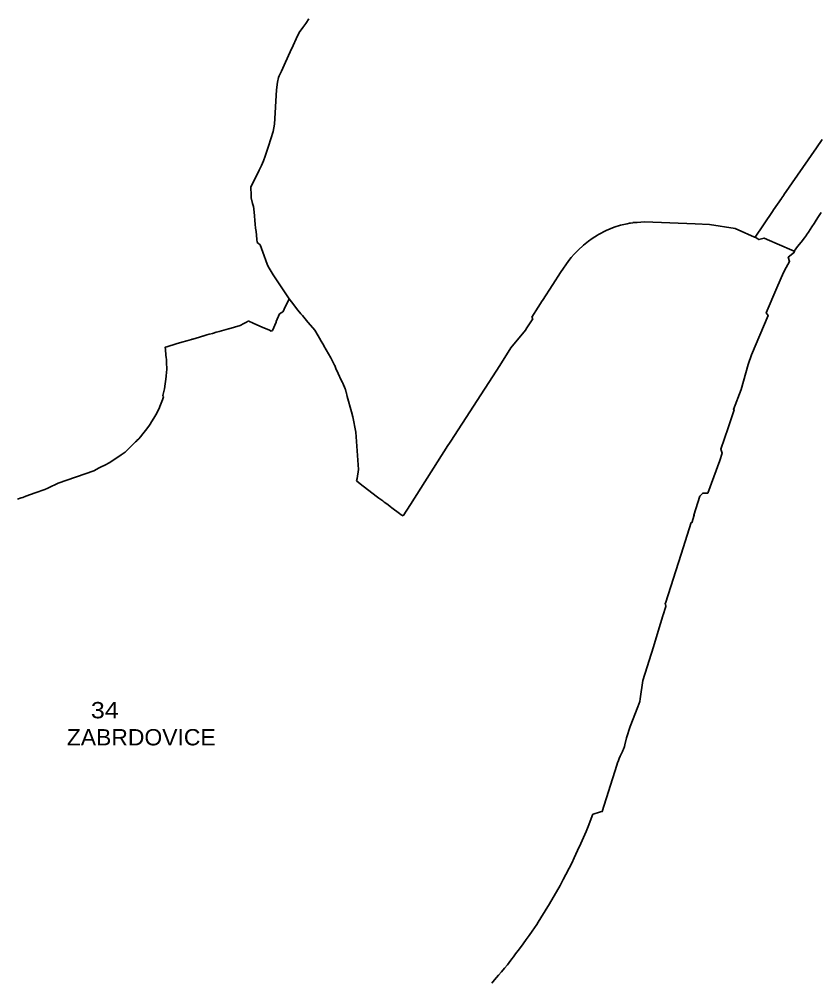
# Model space of a CAD drawing. Extents: x -610940 to -588976, y -1170376 to -1149800.
# Drawn here: x -597067 to -595838, y -1160628 to -1159152 of the extents above; entities that cross this region are included whole.
import ezdxf

# ---------------------------------------------------------------- set-up
doc = ezdxf.new("R2010")
doc.units = 0
doc.header["$LTSCALE"] = 10
doc.layers.add('54', color=7, linetype='Continuous', lineweight=35)
doc.layers.add('55', color=7, linetype='Continuous')
doc.layers.add('56', color=7, linetype='Continuous')

msp = doc.modelspace()

# ---------------------------------------------------------------- linework, layer by layer
at = {"layer": '54'}
for p, q in [((-596622.61, -1159151.93), (-596627.61, -1159158.97)), ((-596670.78, -1159248.89), (-596672.14, -1159260.81)), ((-596669.26, -1159241.48), (-596670.78, -1159248.89)), ((-596668.25, -1159239.42), (-596669.26, -1159241.48)), ((-596672.14, -1159260.81), (-596675.34, -1159313.09)), ((-596677.3, -1159324.73), (-596684.58, -1159347.14)), ((-596675.34, -1159313.09), (-596677.3, -1159324.73)), ((-596702.54, -1159391.38), (-596707.39, -1159401.38)), ((-596711.3, -1159425.25), (-596711.3, -1159426.31)), ((-596707.71, -1159439.7), (-596706.94, -1159443.07)), ((-596706.94, -1159443.07), (-596706.02, -1159454.02)), ((-596706.02, -1159454.02), (-596705.4, -1159460.88)), ((-595912.08, -1159446.96), (-595938.72, -1159486.54)), ((-596705.4, -1159460.88), (-596704.9, -1159466.39)), ((-596704.9, -1159466.39), (-596704.33, -1159472.84)), ((-596166.92, -1159476.5), (-596154.58, -1159471.12)), ((-596154.58, -1159471.12), (-596144.82, -1159468.1)), ((-596144.82, -1159468.1), (-596142.36, -1159467.57)), ((-596142.36, -1159467.57), (-596134.73, -1159465.92)), ((-596134.73, -1159465.92), (-596131.25, -1159465.27)), ((-596131.25, -1159465.27), (-596129.76, -1159465.08)), ((-596129.76, -1159465.08), (-596126.25, -1159464.55)), ((-596126.26, -1159464.26), (-596124.27, -1159464.11)), ((-596126.25, -1159464.55), (-596126.26, -1159464.26)), ((-596124.27, -1159464.11), (-596119.41, -1159463.76)), ((-596119.41, -1159463.76), (-596108.28, -1159462.97)), ((-596108.28, -1159462.97), (-596030.58, -1159465.89)), ((-596030.58, -1159465.89), (-596008.65, -1159467.16)), ((-596008.65, -1159467.16), (-595969.3, -1159473.46)), ((-596704.33, -1159472.84), (-596703.73, -1159477.96)), ((-596703.73, -1159477.96), (-596702.45, -1159489.51)), ((-596188.33, -1159488.39), (-596180.47, -1159483.27)), ((-596180.47, -1159483.27), (-596178.71, -1159482.17)), ((-596178.71, -1159482.17), (-596166.92, -1159476.5)), ((-595969.3, -1159473.46), (-595954.52, -1159479.77)), ((-595954.52, -1159479.77), (-595949.96, -1159481.7)), ((-595949.96, -1159481.7), (-595939.43, -1159486.25)), ((-595939.43, -1159486.25), (-595938.72, -1159486.54)), ((-596702.45, -1159489.51), (-596701.93, -1159494.64)), ((-596701.93, -1159494.64), (-596699.96, -1159496.12)), ((-596699.96, -1159496.12), (-596697.5, -1159498.07)), ((-596697.5, -1159498.07), (-596693.51, -1159509.34)), ((-596209.99, -1159506.34), (-596201.89, -1159498.65)), ((-596201.89, -1159498.65), (-596194.21, -1159492.58)), ((-596194.21, -1159492.58), (-596188.33, -1159488.39)), ((-596693.51, -1159509.34), (-596686.54, -1159527.7)), ((-596220.75, -1159517.91), (-596215.92, -1159512.56)), ((-596215.92, -1159512.56), (-596209.99, -1159506.34)), ((-596686.54, -1159527.7), (-596685.11, -1159531.64)), ((-596237.22, -1159540.52), (-596224.02, -1159522.07)), ((-596224.02, -1159522.07), (-596220.75, -1159517.91)), ((-596685.11, -1159531.64), (-596677.48, -1159544.34)), ((-596677.48, -1159544.34), (-596673.59, -1159550.23)), ((-596248.81, -1159558.89), (-596237.22, -1159540.52)), ((-596673.59, -1159550.23), (-596668.13, -1159558.24)), ((-596668.13, -1159558.24), (-596662.13, -1159567.47)), ((-596264.67, -1159583.62), (-596248.81, -1159558.89)), ((-596662.13, -1159567.47), (-596652.83, -1159581.27)), ((-596660.47, -1159596.66), (-596652.83, -1159581.27)), ((-596652.83, -1159581.27), (-596649.56, -1159585.55)), ((-596649.56, -1159585.55), (-596642.59, -1159594.4)), ((-596271.22, -1159593.87), (-596264.91, -1159584)), ((-596264.91, -1159584), (-596264.67, -1159583.62)), ((-596662.36, -1159600.53), (-596660.47, -1159596.66)), ((-596642.59, -1159594.4), (-596639.92, -1159597.88)), ((-596639.92, -1159597.88), (-596637.13, -1159601.32)), ((-596637.13, -1159601.32), (-596635.14, -1159603.85)), ((-596635.14, -1159603.85), (-596632.74, -1159606.71)), ((-596281.08, -1159609.18), (-596271.22, -1159593.87)), ((-596728.18, -1159621.84), (-596722.26, -1159618.73)), ((-596722.26, -1159618.73), (-596717.36, -1159616.16)), ((-596717.36, -1159616.16), (-596715.74, -1159615.01)), ((-596707.18, -1159618.81), (-596715.74, -1159615.01)), ((-596706.85, -1159618.86), (-596707.18, -1159618.81)), ((-596694.41, -1159624.25), (-596706.85, -1159618.86)), ((-596673.12, -1159616.89), (-596678.57, -1159629.55)), ((-596672.78, -1159616.01), (-596673.12, -1159616.89)), ((-596632.74, -1159606.71), (-596624.17, -1159616.99)), ((-596624.17, -1159616.99), (-596623.82, -1159617.41)), ((-596623.82, -1159617.41), (-596613.43, -1159629.07)), ((-596288.61, -1159625.51), (-596279.48, -1159611.76)), ((-596279.48, -1159611.76), (-596281.08, -1159609.18)), ((-596745.67, -1159626.79), (-596728.18, -1159621.84)), ((-596682.98, -1159629.17), (-596694.41, -1159624.25)), ((-596680.33, -1159630.35), (-596682.98, -1159629.17)), ((-596678.57, -1159629.55), (-596680.33, -1159630.35)), ((-596613.43, -1159629.07), (-596604.99, -1159643.93)), ((-596312.97, -1159656.35), (-596290.81, -1159628.86)), ((-596290.81, -1159628.86), (-596288.61, -1159625.51)), ((-596826.25, -1159649.89), (-596824.65, -1159649.38)), ((-596824.65, -1159649.38), (-596822.46, -1159648.83)), ((-596604.99, -1159643.93), (-596604.21, -1159645.29)), ((-596604.21, -1159645.29), (-596603.95, -1159645.7)), ((-596603.95, -1159645.7), (-596601.51, -1159649.96)), ((-596601.51, -1159649.96), (-596600, -1159652.51)), ((-596600, -1159652.51), (-596599.6, -1159653.28)), ((-596599.6, -1159653.28), (-596596.29, -1159659.04)), ((-596596.29, -1159659.04), (-596596.13, -1159659.35)), ((-596596.13, -1159659.35), (-596589.1, -1159671.61)), ((-596330.09, -1159683.16), (-596312.97, -1159656.35)), ((-596589.1, -1159671.61), (-596583.4, -1159682.61)), ((-596583.4, -1159682.61), (-596583.14, -1159683.31)), ((-596583.14, -1159683.31), (-596581.16, -1159687.69)), ((-596581.16, -1159687.69), (-596577.74, -1159695.26)), ((-596405.27, -1159799.23), (-596335.79, -1159691.87)), ((-596335.79, -1159691.87), (-596330.09, -1159683.16)), ((-596577.74, -1159695.26), (-596573.02, -1159705.51)), ((-596573.02, -1159705.51), (-596571.21, -1159709.48)), ((-596571.21, -1159709.48), (-596570.77, -1159710.41)), ((-596570.77, -1159710.41), (-596566.86, -1159719.06)), ((-596566.86, -1159719.06), (-596566.69, -1159719.63)), ((-596566.69, -1159719.63), (-596565.81, -1159723.06)), ((-596565.81, -1159723.06), (-596565.61, -1159723.77)), ((-596565.61, -1159723.77), (-596563.78, -1159730.55)), ((-596563.78, -1159730.55), (-596557.36, -1159754.38)), ((-596557.36, -1159754.38), (-596555.34, -1159761.89)), ((-596555.34, -1159761.89), (-596550.6, -1159785.52)), ((-596550.6, -1159785.52), (-596546.63, -1159842.66)), ((-596888.42, -1159800.26), (-596902.81, -1159814.44)), ((-596467, -1159896.14), (-596409.48, -1159805.72)), ((-596409.48, -1159805.72), (-596407.06, -1159802.05)), ((-596407.06, -1159802.05), (-596405.27, -1159799.23)), ((-596927.87, -1159831.93), (-596910.5, -1159820.04)), ((-596910.5, -1159820.04), (-596904.56, -1159816.06)), ((-596902.81, -1159814.44), (-596904.56, -1159816.06)), ((-596935.5, -1159835.97), (-596927.87, -1159831.93)), ((-596546.63, -1159842.66), (-596548.93, -1159856.35)), ((-597013.14, -1159866.5), (-597007.32, -1159863.75)), ((-596548.93, -1159856.35), (-596549.59, -1159860.26)), ((-596549.59, -1159860.26), (-596549.23, -1159860.52)), ((-596549.23, -1159860.52), (-596546.98, -1159862.16)), ((-596546.98, -1159862.16), (-596541.49, -1159866.75)), ((-596541.49, -1159866.75), (-596539.64, -1159868.29)), ((-596539.64, -1159868.29), (-596517.64, -1159884.9)), ((-597064, -1159886.29), (-597061.28, -1159885.34)), ((-597056.62, -1159883.72), (-597061.28, -1159885.34)), ((-597027.46, -1159873.28), (-597023.16, -1159871.2)), ((-596517.64, -1159884.9), (-596515.55, -1159886.45)), ((-597069.46, -1159888.21), (-597064, -1159886.29)), ((-596515.55, -1159886.45), (-596509.51, -1159890.91)), ((-596501.2, -1159897.05), (-596506.22, -1159893.22)), ((-596501.2, -1159897.05), (-596498.31, -1159899.21)), ((-596498.31, -1159899.21), (-596495.62, -1159901.25)), ((-596478.34, -1159913.85), (-596467, -1159896.14)), ((-596495.62, -1159901.25), (-596483.57, -1159910.09)), ((-596483.57, -1159910.09), (-596480.99, -1159912.03)), ((-596480.99, -1159912.03), (-596478.34, -1159913.85)), ((-596076.17, -1160054.18), (-596079.59, -1160065.2)), ((-596087.03, -1160090.67), (-596094.54, -1160114.52)), ((-596110.84, -1160166.28), (-596094.54, -1160114.52)), ((-596110.84, -1160166.28), (-596114.89, -1160194.23)), ((-596115.45, -1160198.09), (-596114.89, -1160194.23)), ((-596129.93, -1160236.75), (-596118.5, -1160206.24)), ((-596115.45, -1160198.09), (-596118.5, -1160206.24)), ((-596148.31, -1160288.55), (-596149.48, -1160292.49)), ((-596147, -1160285.62), (-596148.31, -1160288.55)), ((-596187.26, -1160371.06), (-596194.67, -1160389.73)), ((-596175.61, -1160367.65), (-596178.6, -1160368.52)), ((-596237.71, -1160480.57), (-596239.58, -1160484.16)), ((-596271.26, -1160536.44), (-596273.44, -1160540.25))]:
    msp.add_line(p, q, dxfattribs=at)
for points in [[(-596627.61, -1159158.97), (-596631.82, -1159164.98), (-596637.67, -1159172.75), (-596642.09, -1159182.6), (-596646.72, -1159192.51), (-596651.34, -1159202.55), (-596658.67, -1159218.4), (-596664.75, -1159231.79), (-596668.25, -1159239.42)], [(-595835.97, -1159336.96), (-595844.74, -1159349.78), (-595894.52, -1159421.49), (-595894.82, -1159421.93), (-595897.57, -1159425.99), (-595898.38, -1159427.21), (-595910.24, -1159444.37), (-595912.08, -1159446.96)], [(-596684.58, -1159347.14), (-596687.16, -1159354.73), (-596689.66, -1159362.27), (-596692.15, -1159369.66), (-596695.54, -1159376.79), (-596698.99, -1159383.97), (-596702.54, -1159391.38)], [(-596707.39, -1159401.38), (-596711.52, -1159409.99), (-596711.33, -1159422.28)], [(-596711.33, -1159422.28), (-596711.33, -1159422.65), (-596711.3, -1159425.25)], [(-596711.3, -1159426.31), (-596708.93, -1159434.81), (-596707.71, -1159439.7)], [(-595837.14, -1159448.75), (-595841.21, -1159454.77), (-595844.8, -1159460.24), (-595848.32, -1159465.58), (-595851.51, -1159470.44), (-595856.95, -1159478.71), (-595859.82, -1159483.09), (-595859.94, -1159483.24), (-595863.15, -1159487.41), (-595868.23, -1159494.01), (-595873.65, -1159501.06), (-595879.01, -1159508.03)], [(-595938.72, -1159486.54), (-595934.34, -1159489.17), (-595932.74, -1159490.12), (-595924.95, -1159487.91), (-595916.72, -1159491.63), (-595904.67, -1159496.91), (-595879.01, -1159508.03), (-595878.42, -1159509.35), (-595887.8, -1159517.29), (-595885.73, -1159523.63), (-595891.09, -1159533.16), (-595894.98, -1159540.66), (-595900.29, -1159552.54), (-595905.24, -1159564.16), (-595921.49, -1159602.41), (-595918.76, -1159606.62), (-595944.16, -1159666.93), (-595949.42, -1159681.68), (-595959.79, -1159719.99), (-595971.83, -1159750.59), (-595970.72, -1159751.03), (-595980.12, -1159778.83)], [(-596672.78, -1159616.01), (-596667.66, -1159604.22), (-596662.5, -1159600.81), (-596662.36, -1159600.53)], [(-596802.78, -1159643.22), (-596801.44, -1159642.82), (-596800.52, -1159642.66), (-596790.24, -1159639.61), (-596785.75, -1159638.34), (-596785.38, -1159638.22), (-596780.87, -1159636.94), (-596779.26, -1159636.47), (-596775.38, -1159635.35), (-596775.09, -1159635.26), (-596770.56, -1159633.95), (-596769.11, -1159633.54), (-596764.99, -1159632.34), (-596764.54, -1159632.32), (-596760.34, -1159631.01), (-596756.56, -1159629.95), (-596745.95, -1159626.89), (-596745.67, -1159626.79)], [(-596822.46, -1159648.83), (-596817.42, -1159647.39), (-596809.97, -1159645.27), (-596802.78, -1159643.22)], [(-596845.71, -1159731.12), (-596846.38, -1159729.42), (-596843.97, -1159719.2), (-596841.57, -1159699.88), (-596841.48, -1159699.21), (-596840.5, -1159688.66), (-596840.91, -1159678.49), (-596840.96, -1159676.69), (-596840.98, -1159676.01), (-596841.11, -1159673.78), (-596841.45, -1159671.06), (-596841.84, -1159667.44), (-596842.76, -1159658.91), (-596843.12, -1159655.24), (-596840.27, -1159654.41), (-596826.25, -1159649.89)], [(-596888.42, -1159800.26), (-596886.7, -1159798.61), (-596886.38, -1159798.28), (-596883.64, -1159795.43), (-596880.96, -1159792.41), (-596877.1, -1159787.78), (-596873.3, -1159782.97), (-596868.19, -1159776.18), (-596866.11, -1159773.28), (-596863.77, -1159769.7), (-596860.19, -1159763.85), (-596857.29, -1159758.64), (-596855.4, -1159755.1), (-596854.12, -1159752.57), (-596852.47, -1159749.23), (-596851.15, -1159746.19), (-596849.24, -1159741.19), (-596847.25, -1159735.68), (-596845.71, -1159731.12)], [(-595980.12, -1159778.83), (-595991.4, -1159811.54), (-595989.37, -1159817.64), (-595992.53, -1159828.97), (-596011.12, -1159878.87), (-596018.88, -1159878.78), (-596023.56, -1159883.59), (-596032.66, -1159912.5), (-596031.91, -1159912.75), (-596035.82, -1159924.36), (-596036.62, -1159924.12), (-596052.1, -1159972.46)], [(-597007.32, -1159863.75), (-596952.15, -1159844.66), (-596944.42, -1159840.15), (-596940.98, -1159838.69), (-596935.5, -1159835.97)], [(-597023.16, -1159871.2), (-597015.91, -1159867.77), (-597013.14, -1159866.5)], [(-597056.62, -1159883.72), (-597042.42, -1159878.39), (-597027.46, -1159873.28)], [(-596509.51, -1159890.91), (-596507.06, -1159892.58), (-596506.51, -1159893.02), (-596506.22, -1159893.22)], [(-596052.1, -1159972.46), (-596075.93, -1160047.47), (-596076.74, -1160047.67), (-596075.71, -1160052.04), (-596075.63, -1160052.45), (-596076.17, -1160054.18)], [(-596079.59, -1160065.2), (-596079.86, -1160066.24), (-596080.08, -1160066.96), (-596087.03, -1160090.67)], [(-596129.93, -1160236.75), (-596136.03, -1160253.89), (-596138.36, -1160264.73), (-596138.88, -1160267.44), (-596140.61, -1160271.27)], [(-596147, -1160285.62), (-596145.54, -1160282.35), (-596143.11, -1160276.87), (-596142.15, -1160274.72), (-596141.48, -1160273.22), (-596140.61, -1160271.27)], [(-596149.48, -1160292.49), (-596150.55, -1160296.12), (-596173.03, -1160367.02), (-596175.61, -1160367.65)], [(-596178.6, -1160368.52), (-596185.42, -1160370.52), (-596187.26, -1160371.06)], [(-596194.67, -1160389.73), (-596197.76, -1160397.63), (-596201.66, -1160406.81), (-596205.6, -1160415.97), (-596210.76, -1160426.75), (-596215.88, -1160437.81), (-596219.74, -1160445.99), (-596223.71, -1160453.93), (-596228.61, -1160463.68), (-596232.66, -1160471.39), (-596237.71, -1160480.57)], [(-596239.58, -1160484.16), (-596255.28, -1160511.28), (-596256.19, -1160512.76), (-596271.26, -1160536.44)], [(-596273.44, -1160540.25), (-596280.42, -1160550.29), (-596285.02, -1160556.87), (-596289.47, -1160563.29), (-596294.15, -1160569.86), (-596298.2, -1160575.35), (-596298.34, -1160575.47), (-596307.24, -1160587.24), (-596307.28, -1160587.47), (-596312.88, -1160594.71), (-596318.4, -1160601.79), (-596322.81, -1160607.17), (-596327.36, -1160612.51), (-596332, -1160618.07), (-596337.97, -1160625.19), (-596342.19, -1160630.16)]]:
    msp.add_lwpolyline(points, dxfattribs=at)

# ---------------------------------------------------------------- texts
at = {"layer": '55', "width": 1.05}
msp.add_text('ZABRDOVICE ', height=25, dxfattribs=at).set_placement((-596993.81, -1160265.59))
at = {"layer": '56', "width": 1.15}
msp.add_text('34 ', height=25, dxfattribs=at).set_placement((-596956.94, -1160224.07))

doc.saveas('drawing.dxf')
